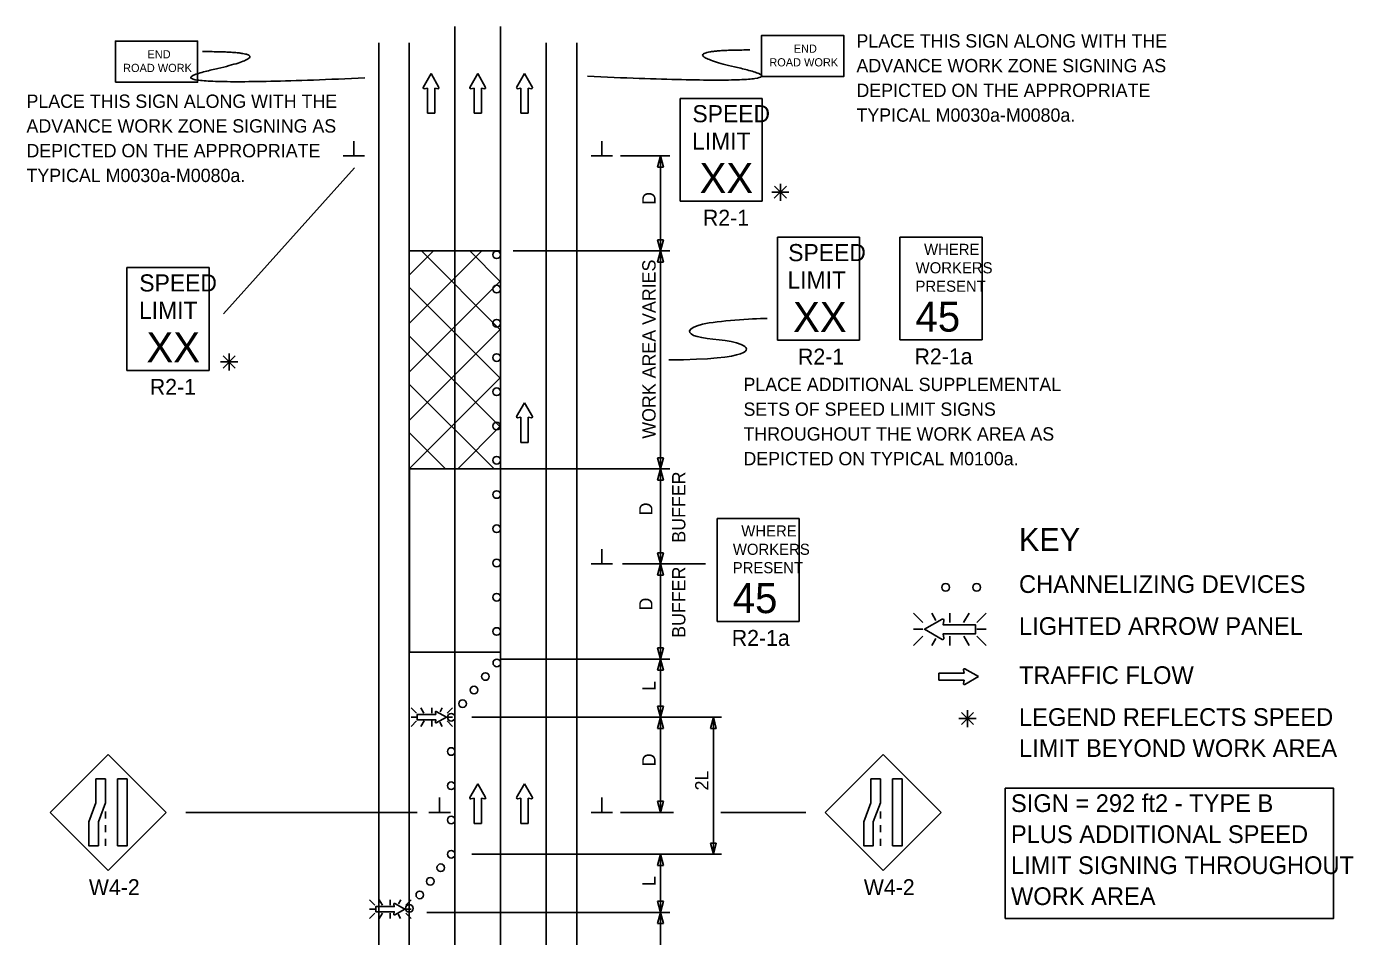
# Model space of a CAD drawing. Extents: x 16731 to 18475, y 5523 to 6928.
# Drawn here: x 16731 to 17429, y 6450 to 6928 of the extents above; entities that cross this region are included whole.
import ezdxf

# ---------------------------------------------------------------- set-up
doc = ezdxf.new("R2010")
doc.units = 0
for name, color, linetype in [('ALI_LEGAL_EX', 7, 'Continuous'), ('MT_SCRATCH_LEVEL_A', 7, 'Continuous'), ('MT_SCRATCH_LEVEL_E', 7, 'Continuous'), ('PAVT_EDGE_EX', 7, 'Continuous'), ('TRAFFIC_SIGNS_PR', 7, 'Continuous'), ('TYPICAL_TEXT_DIMEN_EX', 7, 'Continuous'), ('TYPICAL_TEXT_DIMEN_PR', 7, 'Continuous')]:
    doc.layers.add(name, color=color, linetype=linetype)

msp = doc.modelspace()

# ---------------------------------------------------------------- linework, layer by layer
at = {"layer": 'ALI_LEGAL_EX'}
for p, q in [((16956.63, 6927.83), (16956.63, 6083.69)), ((16980.63, 6927.83), (16980.63, 6083.69))]:
    msp.add_line(p, q, dxfattribs=at)
for points in [[(16956.63, 6919.19), (16956.63, 6902.83)], [(16980.63, 6919.19), (16980.63, 6902.83)], [(16956.63, 6827.83), (16956.63, 6802.83)], [(16980.63, 6827.83), (16980.63, 6802.83)], [(16956.63, 6727.83), (16956.63, 6702.83)], [(16980.63, 6727.83), (16980.63, 6702.83)], [(16956.63, 6627.83), (16956.63, 6602.83)], [(16980.63, 6627.83), (16980.63, 6602.83)], [(16956.63, 6527.83), (16956.63, 6502.83)], [(16980.63, 6527.83), (16980.63, 6502.83)]]:
    msp.add_lwpolyline(points, dxfattribs=at)
at = {"layer": 'MT_SCRATCH_LEVEL_A'}
msp.add_line((16980.63, 6809.85), (16932.63, 6809.85), dxfattribs=at)
at = {"layer": 'MT_SCRATCH_LEVEL_E'}
for p, q in [((16944.07, 6903.1), (16939.96, 6895.86)), ((16948.22, 6895.86), (16944.07, 6903.1)), ((16968.6, 6903.1), (16964.49, 6895.86)), ((16972.75, 6895.86), (16968.6, 6903.1)), ((16993.16, 6903.1), (16989.05, 6895.86)), ((16997.31, 6895.86), (16993.16, 6903.1)), ((16940.44, 6895.17), (16942.22, 6895.49)), ((16942.22, 6895.49), (16942.22, 6882.23)), ((16945.96, 6882.23), (16945.96, 6895.49)), ((16945.96, 6895.49), (16947.74, 6895.17)), ((16964.97, 6895.17), (16966.75, 6895.49)), ((16966.75, 6895.49), (16966.75, 6882.23)), ((16970.49, 6882.23), (16970.49, 6895.49)), ((16970.49, 6895.49), (16972.27, 6895.17)), ((16989.53, 6895.17), (16991.31, 6895.49)), ((16991.31, 6895.49), (16991.31, 6882.23)), ((16995.05, 6882.23), (16995.05, 6895.49)), ((16995.05, 6895.49), (16996.83, 6895.17)), ((16942.22, 6882.23), (16945.96, 6882.23)), ((16966.75, 6882.23), (16970.49, 6882.23)), ((16991.31, 6882.23), (16995.05, 6882.23)), ((16993.16, 6730.05), (16989.05, 6722.81)), ((16997.31, 6722.81), (16993.16, 6730.05)), ((16989.53, 6722.12), (16991.31, 6722.44)), ((16991.31, 6722.44), (16991.31, 6709.18)), ((16995.05, 6709.18), (16995.05, 6722.44)), ((16995.05, 6722.44), (16996.83, 6722.12)), ((16991.31, 6709.18), (16995.05, 6709.18)), ((17224.29, 6587.97), (17211.03, 6587.97)), ((17211.03, 6587.97), (17211.03, 6584.23)), ((17223.97, 6589.74), (17224.29, 6587.97)), ((17231.89, 6586.12), (17224.65, 6590.23)), ((17224.65, 6581.97), (17231.89, 6586.12)), ((17211.03, 6584.23), (17224.29, 6584.23)), ((17224.29, 6584.23), (17223.97, 6582.45)), ((16968.6, 6529.83), (16964.49, 6522.59)), ((16972.75, 6522.59), (16968.6, 6529.83)), ((16993.16, 6529.83), (16989.05, 6522.59)), ((16997.31, 6522.59), (16993.16, 6529.83)), ((16964.97, 6521.91), (16966.75, 6522.22)), ((16966.75, 6522.22), (16966.75, 6508.97)), ((16970.49, 6508.97), (16970.49, 6522.22)), ((16970.49, 6522.22), (16972.27, 6521.91)), ((16989.53, 6521.91), (16991.31, 6522.22)), ((16991.31, 6522.22), (16991.31, 6508.97)), ((16995.05, 6508.97), (16995.05, 6522.22)), ((16995.05, 6522.22), (16996.83, 6521.91)), ((16966.75, 6508.97), (16970.49, 6508.97)), ((16991.31, 6508.97), (16995.05, 6508.97))]:
    msp.add_line(p, q, dxfattribs=at)
for centre, start, end in [((16940.37, 6895.63), 150.42484, 279.96381), ((16947.81, 6895.63), 260.03619, 29.77312), ((16964.9, 6895.63), 150.42484, 279.96381), ((16972.34, 6895.63), 260.03619, 29.77312), ((16989.46, 6895.63), 150.42484, 279.96381), ((16996.9, 6895.63), 260.03619, 29.77312), ((16989.46, 6722.58), 150.42484, 279.96381), ((16996.9, 6722.58), 260.03619, 29.77312), ((17224.43, 6589.82), 60.42484, 189.96381), ((17224.43, 6582.38), 170.03619, 299.77312), ((16964.9, 6522.37), 150.42484, 279.96381), ((16972.34, 6522.37), 260.03619, 29.77312), ((16989.46, 6522.37), 150.42484, 279.96381), ((16996.9, 6522.37), 260.03619, 29.77312)]:
    msp.add_arc(centre, 0.463, start, end, dxfattribs=at)
at = {"layer": 'PAVT_EDGE_EX'}
for p, q in [((16916.63, 6919.19), (16916.63, 6059.77)), ((16932.63, 6919.19), (16932.63, 6059.77)), ((17004.63, 6919.19), (17004.63, 6059.77)), ((17020.63, 6919.19), (17020.63, 6059.77)), ((16980.63, 6809.85), (16932.63, 6809.85)), ((16932.63, 6809.85), (16932.63, 6695.32)), ((16932.63, 6797.14), (16945.35, 6809.85)), ((16932.63, 6771.68), (16970.8, 6809.85)), ((16980.63, 6768.23), (16939.01, 6809.85)), ((16980.63, 6793.69), (16964.47, 6809.85)), ((16932.63, 6746.23), (16980.63, 6794.23)), ((16980.63, 6742.78), (16932.63, 6790.78)), ((16932.63, 6720.77), (16980.63, 6768.77)), ((16980.63, 6717.32), (16932.63, 6765.32)), ((16932.63, 6695.32), (16980.63, 6743.32)), ((16977.18, 6695.32), (16932.63, 6739.86)), ((16958.09, 6695.32), (16980.63, 6717.86)), ((16951.73, 6695.32), (16932.63, 6714.41))]:
    msp.add_line(p, q, dxfattribs=at)
msp.add_lwpolyline([(16980.63, 6695.32), (16932.7, 6695.32), (16932.7, 6599.04), (16980.63, 6599.04)], close=True, dxfattribs=at)
at = {"layer": 'TRAFFIC_SIGNS_PR'}
for p, q in [((17074.95, 6890.04), (17118.15, 6890.04)), ((17074.95, 6836.04), (17074.95, 6890.04)), ((17118.15, 6836.04), (17118.15, 6890.04)), ((17074.95, 6836.04), (17118.15, 6836.04)), ((17126.14, 6817.03), (17169.34, 6817.03)), ((17126.14, 6763.03), (17126.14, 6817.03)), ((17169.34, 6763.03), (17169.34, 6817.03)), ((17190.48, 6817.12), (17233.68, 6817.12)), ((17190.48, 6763.12), (17190.48, 6817.12)), ((17233.68, 6763.12), (17233.68, 6817.12)), ((16784.21, 6801.11), (16827.41, 6801.11)), ((16784.21, 6747.11), (16784.21, 6801.11)), ((16827.41, 6747.11), (16827.41, 6801.11)), ((17126.14, 6763.03), (17169.34, 6763.03)), ((17190.48, 6763.12), (17233.68, 6763.12)), ((16784.21, 6747.11), (16827.41, 6747.11)), ((17094.41, 6669.15), (17137.61, 6669.15)), ((17094.41, 6615.15), (17094.41, 6669.15)), ((17137.61, 6615.15), (17137.61, 6669.15)), ((17197.71, 6619.5), (17202.64, 6614.57)), ((17209.47, 6615.68), (17207.26, 6619.5)), ((17216.79, 6614.57), (17216.79, 6619.5)), ((17224.02, 6614.57), (17226.87, 6619.5)), ((17230.94, 6614.57), (17235.87, 6619.5)), ((17094.41, 6615.15), (17137.61, 6615.15)), ((17202.64, 6611.01), (17197.71, 6611.01)), ((17197.71, 6602.52), (17202.64, 6607.45)), ((17207.22, 6602.52), (17209.33, 6606.18)), ((17216.79, 6607.45), (17216.79, 6602.52)), ((17226.92, 6602.52), (17224.07, 6607.45)), ((17230.94, 6611.01), (17235.87, 6611.01)), ((17230.94, 6607.45), (17235.87, 6602.52)), ((16936.41, 6566.86), (16933.59, 6569.68)), ((16936.41, 6564.82), (16933.59, 6564.82)), ((16938.71, 6569.68), (16940.33, 6566.86)), ((16944.49, 6566.86), (16944.49, 6569.68)), ((16949.96, 6569.68), (16948.76, 6567.58)), ((16955.4, 6569.67), (16952.58, 6566.86)), ((16952.58, 6564.82), (16955.4, 6564.82)), ((16936.41, 6562.79), (16933.59, 6559.97)), ((16940.36, 6562.79), (16938.73, 6559.97)), ((16944.49, 6562.79), (16944.49, 6559.97)), ((16948.68, 6562.16), (16949.94, 6559.97)), ((16955.4, 6559.97), (16952.58, 6562.79)), ((16774.34, 6545.2), (16743.8, 6514.65)), ((16804.89, 6514.65), (16774.34, 6545.2)), ((17181.7, 6545.2), (17151.16, 6514.65)), ((17212.25, 6514.65), (17181.7, 6545.2)), ((16772.94, 6515.21), (16772.94, 6511.61)), ((17180.3, 6515.21), (17180.3, 6511.61)), ((16743.8, 6514.65), (16774.34, 6484.11)), ((16772.94, 6508.01), (16772.94, 6504.41)), ((16774.34, 6484.11), (16804.89, 6514.65)), ((17151.16, 6514.65), (17181.7, 6484.11)), ((17180.3, 6508.01), (17180.3, 6504.41)), ((17181.7, 6484.11), (17212.25, 6514.65)), ((16772.94, 6500.81), (16772.94, 6497.21)), ((17180.3, 6500.81), (17180.3, 6497.21)), ((16914.54, 6465.9), (16911.72, 6468.72)), ((16916.83, 6468.72), (16918.46, 6465.9)), ((16922.62, 6465.9), (16922.62, 6468.72)), ((16928.09, 6468.72), (16926.88, 6466.63)), ((16933.53, 6468.72), (16930.71, 6465.9)), ((16914.54, 6463.87), (16911.72, 6463.87)), ((16914.54, 6461.84), (16911.72, 6459.02)), ((16918.49, 6461.84), (16916.86, 6459.02)), ((16922.62, 6461.84), (16922.62, 6459.02)), ((16926.8, 6461.2), (16928.06, 6459.02)), ((16930.71, 6463.87), (16933.53, 6463.87)), ((16933.53, 6459.02), (16930.71, 6461.84))]:
    msp.add_line(p, q, dxfattribs=at)
for points in [[(16778.1, 6898.58), (16821.31, 6898.58), (16821.31, 6920.18), (16778.1, 6920.18)], [(17117.81, 6901.54), (17161.01, 6901.54), (17161.01, 6923.14), (17117.81, 6923.14)], [(16772.94, 6532.36), (16772.94, 6519.78), (16769.18, 6509.79), (16769.18, 6497.21), (16764.12, 6497.21), (16764.12, 6509.79), (16767.88, 6519.78), (16767.88, 6532.36)], [(16784.34, 6532.36), (16784.34, 6497.21), (16779.29, 6497.21), (16779.29, 6532.36)], [(17180.3, 6532.36), (17180.3, 6519.78), (17176.54, 6509.79), (17176.54, 6497.21), (17171.48, 6497.21), (17171.48, 6509.79), (17175.24, 6519.78), (17175.24, 6532.36)], [(17191.7, 6532.36), (17191.7, 6497.21), (17186.65, 6497.21), (17186.65, 6532.36)]]:
    msp.add_lwpolyline(points, close=True, dxfattribs=at)
for points in [[(17212.72, 6616.29), (17203.43, 6611.01), (17212.72, 6605.69)], [(17213.59, 6606.32), (17213.19, 6608.58), (17230.2, 6608.58), (17230.2, 6613.39), (17213.19, 6613.39), (17213.59, 6615.67)], [(16946.32, 6567.51), (16946.55, 6566.21), (16936.83, 6566.21), (16936.83, 6563.47), (16946.55, 6563.47), (16946.32, 6562.16)], [(16946.82, 6561.81), (16952.13, 6564.82), (16946.82, 6567.86)], [(16924.45, 6466.55), (16924.68, 6465.26), (16914.96, 6465.26), (16914.96, 6462.51), (16924.68, 6462.51), (16924.45, 6461.21)], [(16924.95, 6460.86), (16930.26, 6463.87), (16924.95, 6466.91)]]:
    msp.add_lwpolyline(points, dxfattribs=at)
for centre in [(16978.53, 6807.84), (16978.53, 6789.84), (16978.53, 6771.84), (16978.53, 6753.84), (16978.53, 6735.84), (16978.53, 6717.84), (16978.53, 6699.84), (16978.53, 6681.84), (16978.53, 6663.84), (16978.53, 6645.84), (17214.57, 6633.04), (17230.87, 6633.04), (16978.53, 6627.84), (16978.53, 6609.84), (16978.63, 6593.32), (16972.63, 6586.17), (16966.63, 6579.03), (16960.63, 6571.89), (16954.63, 6564.75), (16954.63, 6546.75), (16954.63, 6528.75), (16954.63, 6510.75), (16954.63, 6492.75), (16949.14, 6485.62), (16943.64, 6478.49), (16938.14, 6471.36), (16932.64, 6464.24)]:
    msp.add_circle(centre, 2, dxfattribs=at)
for centre, radius, start, end in [((17213, 6615.76), 0.598, 350.73078, 118.89165), ((17213, 6606.21), 0.597, 241.48329, 9.95933), ((16946.66, 6567.56), 0.341, 61.48329, 189.95933), ((16946.66, 6562.11), 0.341, 170.73078, 298.89165), ((16924.78, 6466.61), 0.341, 61.48329, 189.95933), ((16924.78, 6461.16), 0.341, 170.73078, 298.89165)]:
    msp.add_arc(centre, radius, start, end, dxfattribs=at)
for points in [[(16823.94, 6914.67), (16871.17, 6914.67), (16786.15, 6895.33), (16909.25, 6900.82)], [(17111.64, 6915.52), (17064.41, 6915.52), (17149.43, 6896.18), (17026.33, 6901.67)]]:
    msp.add_open_spline(points, degree=2, dxfattribs=at)
at = {"layer": 'TYPICAL_TEXT_DIMEN_EX'}
msp.add_lwpolyline([(17245.88, 6527.45), (17418.47, 6527.45), (17418.47, 6459.03), (17245.88, 6459.03)], close=True, dxfattribs=at)
at = {"layer": 'TYPICAL_TEXT_DIMEN_PR'}
for p, q in [((16903.51, 6859.85), (16903.51, 6867.64)), ((17033.76, 6859.85), (17033.76, 6867.64)), ((16897.88, 6859.85), (16909.13, 6859.85)), ((17039.38, 6859.85), (17028.13, 6859.85)), ((17069.63, 6859.85), (17043.63, 6859.85)), ((17063.06, 6853.99), (17064.63, 6859.85)), ((17064.63, 6859.85), (17064.63, 6809.85)), ((17064.63, 6859.85), (17066.2, 6853.99)), ((16835.02, 6776.73), (16903.75, 6853.59)), ((17064.63, 6853.99), (17063.06, 6853.99)), ((17066.2, 6853.99), (17064.63, 6853.99)), ((17130.88, 6843.94), (17124.5, 6837.56)), ((17124.51, 6843.94), (17130.88, 6837.56)), ((17127.69, 6840.75), (17127.69, 6845.21)), ((17127.69, 6840.75), (17123.16, 6840.75)), ((17127.69, 6840.75), (17130.88, 6840.75)), ((17127.69, 6840.75), (17132.17, 6840.75)), ((17127.69, 6840.75), (17127.69, 6836.25)), ((17064.63, 6809.85), (17063.06, 6815.71)), ((17063.06, 6815.71), (17064.63, 6815.71)), ((17064.63, 6815.71), (17066.2, 6815.71)), ((17066.2, 6815.71), (17064.63, 6809.85)), ((17069.63, 6809.85), (16987.24, 6809.85)), ((17063.06, 6803.99), (17064.63, 6809.85)), ((17064.63, 6695.32), (17064.63, 6809.85)), ((17064.63, 6809.85), (17066.2, 6803.99)), ((17064.63, 6803.99), (17063.06, 6803.99)), ((17066.2, 6803.99), (17064.63, 6803.99)), ((16834.73, 6754.69), (16841.11, 6748.32)), ((16841.11, 6754.69), (16834.73, 6748.32)), ((16837.92, 6751.51), (16837.92, 6755.96)), ((16837.92, 6751.51), (16833.39, 6751.51)), ((16837.92, 6751.51), (16841.11, 6751.51)), ((16837.92, 6751.51), (16842.4, 6751.51)), ((16837.92, 6751.51), (16837.92, 6747.01)), ((17064.63, 6695.32), (17063.06, 6701.18)), ((17063.06, 6701.18), (17064.63, 6701.18)), ((17064.63, 6701.18), (17066.2, 6701.18)), ((17066.2, 6701.18), (17064.63, 6695.32)), ((17069.63, 6695.32), (16980.63, 6695.32)), ((17063.06, 6689.45), (17064.63, 6695.32)), ((17064.63, 6689.45), (17063.06, 6689.45)), ((17064.63, 6645.32), (17064.63, 6695.32)), ((17064.63, 6695.32), (17066.2, 6689.45)), ((17066.2, 6689.45), (17064.63, 6689.45)), ((17033.76, 6645.32), (17033.76, 6653.1)), ((17064.63, 6645.32), (17063.06, 6651.18)), ((17063.06, 6651.18), (17064.63, 6651.18)), ((17064.63, 6651.18), (17066.2, 6651.18)), ((17066.2, 6651.18), (17064.63, 6645.32)), ((17039.38, 6645.32), (17028.13, 6645.32)), ((17088.4, 6645.32), (17044.65, 6645.32)), ((17063.06, 6639.45), (17064.63, 6645.32)), ((17064.63, 6595.32), (17064.63, 6645.32)), ((17064.63, 6645.32), (17066.2, 6639.45)), ((17064.63, 6639.45), (17063.06, 6639.45)), ((17066.2, 6639.45), (17064.63, 6639.45)), ((17064.63, 6595.32), (17063.06, 6601.18)), ((17063.06, 6601.18), (17064.63, 6601.18)), ((17064.63, 6601.18), (17066.2, 6601.18)), ((17066.2, 6601.18), (17064.63, 6595.32)), ((17069.63, 6595.32), (16980.63, 6595.32)), ((17063.06, 6589.45), (17064.63, 6595.32)), ((17064.63, 6564.75), (17064.63, 6595.32)), ((17064.63, 6595.32), (17066.2, 6589.45)), ((17064.63, 6589.45), (17063.06, 6589.45)), ((17066.2, 6589.45), (17064.63, 6589.45)), ((17096.68, 6564.75), (16965.53, 6564.75)), ((17064.63, 6564.75), (17063.06, 6570.61)), ((17063.06, 6570.61), (17064.63, 6570.61)), ((17063.06, 6558.89), (17064.63, 6564.75)), ((17064.63, 6570.61), (17066.2, 6570.61)), ((17066.2, 6570.61), (17064.63, 6564.75)), ((17064.63, 6564.75), (17064.63, 6514.75)), ((17064.63, 6564.75), (17066.2, 6558.89)), ((17090.87, 6558.89), (17092.44, 6564.75)), ((17092.44, 6564.75), (17094.01, 6558.89)), ((17092.44, 6564.75), (17092.44, 6492.75)), ((17226.05, 6564.1), (17221.51, 6564.1)), ((17222.86, 6567.29), (17229.23, 6560.91)), ((17229.23, 6567.29), (17222.86, 6560.91)), ((17226.05, 6564.1), (17226.05, 6568.55)), ((17226.05, 6564.1), (17229.23, 6564.1)), ((17226.05, 6564.1), (17230.52, 6564.1)), ((17226.05, 6564.1), (17226.05, 6559.6)), ((17064.63, 6558.89), (17063.06, 6558.89)), ((17066.2, 6558.89), (17064.63, 6558.89)), ((17092.44, 6558.89), (17090.87, 6558.89)), ((17094.01, 6558.89), (17092.44, 6558.89)), ((16948.56, 6514.75), (16948.56, 6522.54)), ((17033.76, 6514.75), (17033.76, 6522.54)), ((17064.63, 6514.75), (17063.06, 6520.61)), ((17063.06, 6520.61), (17064.63, 6520.61)), ((17064.63, 6520.61), (17066.2, 6520.61)), ((17066.2, 6520.61), (17064.63, 6514.75)), ((16815.08, 6514.75), (16936.83, 6514.75)), ((16954.19, 6514.75), (16942.94, 6514.75)), ((17039.38, 6514.75), (17028.13, 6514.75)), ((17071.43, 6514.75), (17043.63, 6514.75)), ((17141.08, 6514.75), (17096.37, 6514.75)), ((17092.44, 6492.75), (17090.87, 6498.61)), ((17090.87, 6498.61), (17092.44, 6498.61)), ((17092.44, 6498.61), (17094.01, 6498.61)), ((17094.01, 6498.61), (17092.44, 6492.75)), ((16965.53, 6492.75), (17096.68, 6492.75)), ((17063.06, 6486.89), (17064.63, 6492.75)), ((17064.63, 6462.19), (17064.63, 6492.75)), ((17064.63, 6492.75), (17066.2, 6486.89)), ((17064.63, 6486.89), (17063.06, 6486.89)), ((17066.2, 6486.89), (17064.63, 6486.89)), ((17064.63, 6462.19), (17063.06, 6468.05)), ((17063.06, 6468.05), (17064.63, 6468.05)), ((17064.63, 6468.05), (17066.2, 6468.05)), ((17066.2, 6468.05), (17064.63, 6462.19)), ((16941.8, 6462.19), (17069.63, 6462.19)), ((17063.06, 6456.33), (17064.63, 6462.19)), ((17064.63, 6462.19), (17064.63, 6412.19)), ((17064.63, 6462.19), (17066.2, 6456.33)), ((17064.63, 6456.33), (17063.06, 6456.33)), ((17066.2, 6456.33), (17064.63, 6456.33))]:
    msp.add_line(p, q, dxfattribs=at)
msp.add_open_spline([(17068.99, 6752.6), (17113.1, 6752.91), (17112.74, 6763.34), (17078.18, 6763.34), (17078.18, 6772.39), (17112.39, 6774.15), (17120.68, 6774.44)], degree=3, dxfattribs=at)

# ---------------------------------------------------------------- texts
at = {"layer": 'TRAFFIC_SIGNS_PR'}
for s, height, p in [('PLACE THIS SIGN ALONG WITH THE', 7, (17167.68, 6916.8)), ('END', 4.31, (16794.98, 6911.1)), ('END', 4.31, (17134.69, 6914.06)), ('ROAD WORK', 4.31, (16782.16, 6903.92)), ('ROAD WORK', 4.31, (17121.87, 6906.87)), ('ADVANCE WORK ZONE SIGNING AS', 7, (17167.68, 6903.8)), ('PLACE THIS SIGN ALONG WITH THE', 7, (16731.39, 6885.09)), ('DEPICTED ON THE APPROPRIATE', 7, (17167.68, 6890.8)), ('SPEED', 9, (17081.44, 6877.51)), ('TYPICAL M0030a-M0080a.', 7, (17167.68, 6877.8)), ('ADVANCE WORK ZONE SIGNING AS', 7, (16731.39, 6872.09)), ('LIMIT', 9, (17081.26, 6863.11)), ('DEPICTED ON THE APPROPRIATE', 7, (16731.39, 6859.09)), ('TYPICAL M0030a-M0080a.', 7, (16731.39, 6846.09)), ('XX', 15.785, (17085.2, 6840.27)), ('R2-1', 8.37, (17086.96, 6823.17)), ('SPEED', 9, (17131.8, 6804.5)), ('WHERE', 5.85, (17203.21, 6807.77)), ('WORKERS', 5.85, (17198.79, 6798.09)), ('SPEED', 9, (16790.69, 6788.57)), ('LIMIT', 9, (17131.43, 6790.1)), ('PRESENT', 5.85, (17198.71, 6788.42)), ('LIMIT', 9, (16790.51, 6774.18)), ('XX', 15.785, (17134.36, 6767.25)), ('45', 15.785, (17198.7, 6767.46)), ('XX', 15.785, (16794.46, 6751.33)), ('R2-1', 8.37, (17136.95, 6750.16)), ('R2-1a', 8.37, (17198.19, 6750.25)), ('R2-1', 8.37, (16796.22, 6734.24)), ('PLACE ADDITIONAL SUPPLEMENTAL', 7, (17108.29, 6736.2)), ('SETS OF SPEED LIMIT SIGNS', 7, (17108.29, 6723.2)), ('THROUGHOUT THE WORK AREA AS', 7, (17108.29, 6710.2)), ('DEPICTED ON TYPICAL M0100a.', 7, (17108.29, 6697.2)), ('WHERE', 5.85, (17107.13, 6659.8)), ('WORKERS', 5.85, (17102.71, 6650.12)), ('PRESENT', 5.85, (17102.64, 6640.45)), ('45', 15.785, (17102.63, 6619.49)), ('R2-1a', 8.37, (17102.12, 6602.28)), ('W4-2', 8.37, (16764.17, 6471.24)), ('W4-2', 8.37, (17171.53, 6471.24))]:
    msp.add_text(s, height=height, dxfattribs=at).set_placement(p)
at = {"layer": 'TYPICAL_TEXT_DIMEN_EX'}
for s, height, p in [('KEY', 12, (17253.11, 6652.15)), ('CHANNELIZING DEVICES', 9.3, (17253.11, 6630.1)), ('LIGHTED ARROW PANEL', 9.3, (17253.11, 6608.05)), ('TRAFFIC FLOW', 9.3, (17253.11, 6582.25)), ('LEGEND REFLECTS SPEED', 9.3, (17253.11, 6560.2)), ('LIMIT BEYOND WORK AREA', 9.3, (17253.11, 6543.9)), ('SIGN = 292 ft2 - TYPE B', 9.3, (17248.89, 6514.95)), ('PLUS ADDITIONAL SPEED', 9.3, (17248.89, 6498.65)), ('LIMIT SIGNING THROUGHOUT', 9.3, (17248.89, 6482.35)), ('WORK AREA', 9.3, (17248.89, 6466.05))]:
    msp.add_text(s, height=height, dxfattribs=at).set_placement(p)
at = {"layer": 'TYPICAL_TEXT_DIMEN_PR'}
for s, p in [('D', (17062.08, 6834.07)), ('WORK AREA VARIES', (17062.08, 6711.17)), ('BUFFER', (17077.75, 6656.51)), ('D', (17060.45, 6670.87)), ('BUFFER', (17077.75, 6606.51)), ('D', (17060.45, 6620.87)), ('L', (17062.08, 6578.61)), ('D', (17062.08, 6538.97)), ('2L', (17089.88, 6526.26)), ('L', (17062.08, 6476.05))]:
    msp.add_text(s, height=7, rotation=90, dxfattribs=at).set_placement(p)

doc.saveas('drawing.dxf')
